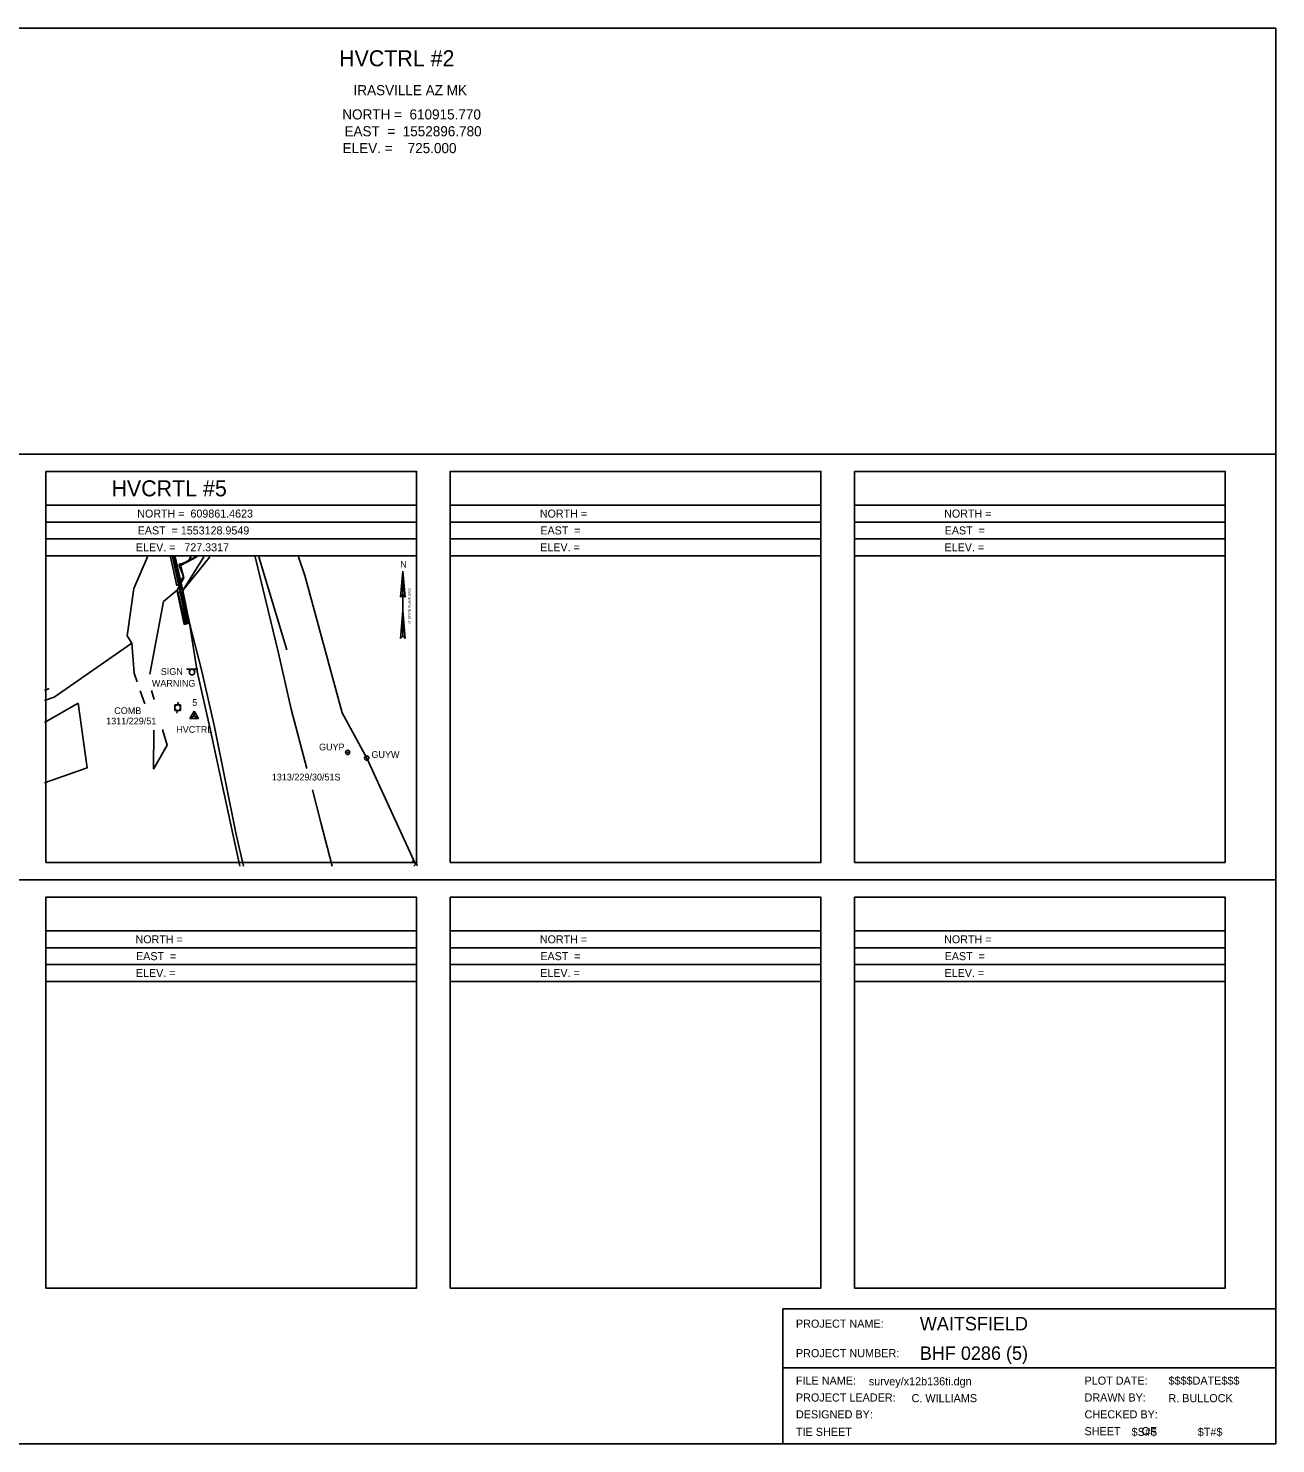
# Model space of a CAD drawing. Extents: x 1553683 to 1554323, y 609712 to 610132.
# Drawn here: x 1553952.8 to 1554323, y 609712.3 to 610132.3 of the extents above; entities that cross this region are included whole.
import ezdxf

# ---------------------------------------------------------------- set-up
doc = ezdxf.new("R2010")
doc.units = 0
for name, color, linetype in [('BDC', 7, 'Continuous'), ('BELB', 7, 'Continuous'), ('BF', 7, 'Continuous'), ('BFT', 7, 'Continuous'), ('BR', 7, 'Continuous'), ('BSE', 7, 'Continuous'), ('BSUBM', 7, 'Continuous'), ('C_A', 7, 'Continuous'), ('C_I', 7, 'Continuous'), ('CPSM', 7, 'Continuous'), ('L_TIC', 7, 'Continuous'), ('LARO', 7, 'Continuous'), ('LAWA', 7, 'Continuous'), ('LAWE', 7, 'Continuous'), ('LELB', 7, 'Continuous'), ('NBL1', 7, 'Continuous'), ('NBL2', 7, 'Continuous'), ('NNA_P', 7, 'Continuous'), ('PET', 7, 'Continuous'), ('RC', 7, 'Continuous'), ('RGR', 7, 'Continuous'), ('S_A', 7, 'Continuous'), ('S_C', 7, 'Continuous'), ('SSGN', 7, 'Continuous'), ('U_A', 7, 'Continuous'), ('U_C', 7, 'Continuous'), ('UP', 7, 'Continuous'), ('UPGW', 7, 'Continuous')]:
    doc.layers.add(name, color=color, linetype=linetype)

msp = doc.modelspace()

# ---------------------------------------------------------------- linework, layer by layer
at = {"layer": 'BDC'}
msp.add_lwpolyline([(1553998.14, 609965.46), (1553995.94, 609975.51)], dxfattribs=at)
at = {"layer": 'BELB'}
for points in [[(1553998.6, 609965.49), (1553996.37, 609975.51)], [(1554004.9, 609975.51), (1553998.6, 609965.49)]]:
    msp.add_lwpolyline(points, dxfattribs=at)
at = {"layer": 'BF'}
msp.add_lwpolyline([(1553994.94, 609975.51), (1553996.84, 609966.88)], dxfattribs=at)
at = {"layer": 'BFT'}
for points in [[(1554000.87, 609975.51), (1554000.67, 609974.99), (1554000.47, 609974.55), (1553998.99, 609973.67), (1553997.4, 609973.19)], [(1554000.36, 609974.24), (1554001.15, 609975.51)]]:
    msp.add_lwpolyline(points, dxfattribs=at)
at = {"layer": 'BR'}
msp.add_lwpolyline([(1553997.86, 609965.15), (1553995.57, 609975.51)], dxfattribs=at)
at = {"layer": 'BSE'}
for points in [[(1554002.85, 609975.51), (1554002.83, 609975.48), (1553997.89, 609972.93)], [(1553998.96, 609969.31), (1553997.89, 609972.93)], [(1553998.96, 609969.31), (1553997.18, 609966.03), (1553997.01, 609965.66)]]:
    msp.add_lwpolyline(points, dxfattribs=at)
at = {"layer": 'BSUBM'}
for points in [[(1554002.37, 609975.51), (1554000.36, 609974.24)], [(1553998.78, 609969.64), (1553997.4, 609973.19)], [(1553997.03, 609966.91), (1553998.78, 609969.64)], [(1553997.01, 609965.66), (1553997.05, 609964.77), (1553999.05, 609955.45), (1554000.57, 609955.79)]]:
    msp.add_lwpolyline(points, dxfattribs=at)
at = {"layer": 'CPSM'}
for p, q in [((1554000.73, 609927.55), (1554001.98, 609929.72)), ((1554000.73, 609927.55), (1554001.98, 609928.27)), ((1554003.23, 609927.55), (1554001.98, 609929.72)), ((1554001.98, 609928.27), (1554001.98, 609929.72)), ((1554001.98, 609928.27), (1554001.98, 609928.27)), ((1554001.98, 609928.27), (1554003.23, 609927.55)), ((1554000.73, 609927.55), (1554003.23, 609927.55))]:
    msp.add_line(p, q, dxfattribs=at)
at = {"layer": 'L_TIC'}
for points in [[(1554068.23, 609883.76), (1554066.72, 609885.27)], [(1554067.14, 609883.68), (1554068.23, 609884.78)], [(1554067.14, 609883.68), (1554068.23, 609884.78)]]:
    msp.add_lwpolyline(points, dxfattribs=at)
at = {"layer": 'LARO'}
for points in [[(1553988.16, 609975.51), (1553984.05, 609966.14), (1553982.1, 609952.03), (1553983.46, 609949.84)], [(1553988.88, 609940.66), (1553992.85, 609962.22), (1553997.01, 609965.66)], [(1553984.19, 609940.93), (1553983.46, 609949.84)], [(1553985.06, 609938.42), (1553984.19, 609940.93)], [(1553987.34, 609931.84), (1553986, 609935.72)], [(1553990.07, 609933.13), (1553989.28, 609935.87)], [(1553989.97, 609912.47), (1553993.96, 609919.56), (1553992.62, 609924.22)], [(1553989.97, 609912.47), (1553990.04, 609924.06)]]:
    msp.add_lwpolyline(points, dxfattribs=at)
at = {"layer": 'LAWA'}
for points in [[(1554032.99, 609975.51), (1554034.79, 609969.93), (1554045.95, 609929.17), (1554053.21, 609915.78), (1554067.72, 609884.27), (1554068.23, 609884.03)], [(1553957.55, 609926.36), (1553967.6, 609932.09)], [(1553957.55, 609908.39), (1553970.2, 609912.87), (1553967.6, 609932.09)]]:
    msp.add_lwpolyline(points, dxfattribs=at)
at = {"layer": 'LAWE'}
msp.add_lwpolyline([(1553983.46, 609949.84), (1553960.43, 609933.88), (1553957.55, 609932.82)], dxfattribs=at)
at = {"layer": 'LELB'}
msp.add_lwpolyline([(1553959, 609936.45), (1553957.55, 609935.87)], dxfattribs=at)
at = {"layer": 'NBL1'}
msp.add_line((1554176.73, 609734.83), (1554322.98, 609734.83), dxfattribs=at)
msp.add_lwpolyline([(1553682.98, 609712.33), (1554322.98, 609712.33), (1554322.98, 610132.33), (1553682.98, 610132.33)], close=True, dxfattribs=at)
msp.add_lwpolyline([(1554322.98, 609752.33), (1554176.73, 609752.33), (1554176.73, 609712.33)], dxfattribs=at)
at = {"layer": 'NBL2'}
for p, q in [((1553682.98, 610005.99), (1554322.98, 610005.99)), ((1554067.98, 609990.83), (1553957.98, 609990.83)), ((1554187.98, 609990.83), (1554077.98, 609990.83)), ((1554307.98, 609990.83), (1554197.98, 609990.83)), ((1554067.98, 609985.83), (1553957.98, 609985.83)), ((1554187.98, 609985.83), (1554077.98, 609985.83)), ((1554307.98, 609985.83), (1554197.98, 609985.83)), ((1554067.98, 609980.83), (1553957.98, 609980.83)), ((1554187.98, 609980.83), (1554077.98, 609980.83)), ((1554307.98, 609980.83), (1554197.98, 609980.83)), ((1554067.98, 609975.83), (1553957.98, 609975.83)), ((1554187.98, 609975.83), (1554077.98, 609975.83)), ((1554307.98, 609975.83), (1554197.98, 609975.83)), ((1553682.98, 609879.66), (1554322.98, 609879.66)), ((1554067.98, 609864.49), (1553957.98, 609864.49)), ((1554187.98, 609864.49), (1554077.98, 609864.49)), ((1554307.98, 609864.49), (1554197.98, 609864.49)), ((1554067.98, 609859.49), (1553957.98, 609859.49)), ((1554187.98, 609859.49), (1554077.98, 609859.49)), ((1554307.98, 609859.49), (1554197.98, 609859.49)), ((1554067.98, 609854.49), (1553957.98, 609854.49)), ((1554187.98, 609854.49), (1554077.98, 609854.49)), ((1554307.98, 609854.49), (1554197.98, 609854.49)), ((1554067.98, 609849.49), (1553957.98, 609849.49)), ((1554187.98, 609849.49), (1554077.98, 609849.49)), ((1554307.98, 609849.49), (1554197.98, 609849.49))]:
    msp.add_line(p, q, dxfattribs=at)
for points in [[(1553957.98, 609884.83), (1554067.98, 609884.83), (1554067.98, 610000.83), (1553957.98, 610000.83)], [(1554077.98, 609884.83), (1554187.98, 609884.83), (1554187.98, 610000.83), (1554077.98, 610000.83)], [(1554197.98, 609884.83), (1554307.98, 609884.83), (1554307.98, 610000.83), (1554197.98, 610000.83)], [(1553957.98, 609758.49), (1554067.98, 609758.49), (1554067.98, 609874.49), (1553957.98, 609874.49)], [(1554077.98, 609758.49), (1554187.98, 609758.49), (1554187.98, 609874.49), (1554077.98, 609874.49)], [(1554197.98, 609758.49), (1554307.98, 609758.49), (1554307.98, 609874.49), (1554197.98, 609874.49)]]:
    msp.add_lwpolyline(points, close=True, dxfattribs=at)
at = {"layer": 'NNA_P'}
for p, q in [((1554063.21, 609963.5), (1554063.91, 609971.29)), ((1554063.91, 609951.92), (1554063.91, 609971.29)), ((1554064.6, 609963.5), (1554063.91, 609971.29)), ((1554063.21, 609963.5), (1554063.91, 609964.27)), ((1554064.6, 609963.5), (1554063.91, 609964.27)), ((1554063.91, 609959.44), (1554063.19, 609951.28)), ((1554063.91, 609959.44), (1554064.63, 609951.28)), ((1554063.91, 609951.92), (1554063.19, 609951.28)), ((1554063.91, 609951.92), (1554064.63, 609951.28))]:
    msp.add_line(p, q, dxfattribs=at)
at = {"layer": 'PET'}
for points in [[(1554016.61, 609883.68), (1554014.46, 609893.13), (1554007.99, 609925.03), (1554004.12, 609941.99), (1554000.57, 609955.79), (1553998.6, 609965.49), (1554006.66, 609975.51)], [(1554035.43, 609912.68), (1554030.82, 609930.31), (1554027.01, 609946.9), (1554020.09, 609975.51)], [(1554042.94, 609883.68), (1554039.62, 609896.63), (1554037.07, 609906.38)]]:
    msp.add_lwpolyline(points, dxfattribs=at)
at = {"layer": 'RC'}
for points in [[(1554000.23, 609955.99), (1553999.75, 609955.86), (1553999.32, 609955.74), (1553997.26, 609964.93), (1553997.86, 609965.15), (1553998.22, 609965.18)], [(1554000.23, 609955.99), (1553998.22, 609965.18)]]:
    msp.add_lwpolyline(points, dxfattribs=at)
at = {"layer": 'RGR'}
for points in [[(1554029.52, 609947.9), (1554021.14, 609975.51)], [(1553999.75, 609955.86), (1553997.86, 609965.15)], [(1554015.59, 609883.68), (1554013.58, 609892.8), (1554006.64, 609924.87), (1554002.84, 609941.47), (1554000.57, 609955.79)]]:
    msp.add_lwpolyline(points, dxfattribs=at)
at = {"layer": 'SSGN'}
for p, q in [((1553999.71, 609942.12), (1554003.04, 609942.12)), ((1554001.35, 609941.29), (1554001.35, 609941.29))]:
    msp.add_line(p, q, dxfattribs=at)
msp.add_circle((1554001.35, 609941.29), 0.833, dxfattribs=at)
at = {"layer": 'UP'}
for p, q in [((1553997.32, 609932.4), (1553997.07, 609931.57)), ((1553996.24, 609929.9), (1553996.24, 609931.57)), ((1553996.24, 609931.57), (1553997.91, 609931.57)), ((1553997.91, 609929.9), (1553996.24, 609929.9)), ((1553996.82, 609929.07), (1553997.07, 609929.9)), ((1553997.07, 609930.74), (1553997.07, 609930.74)), ((1553997.91, 609931.57), (1553997.91, 609929.9))]:
    msp.add_line(p, q, dxfattribs=at)
msp.add_circle((1553997.07, 609930.74), 0.833, dxfattribs=at)
at = {"layer": 'UPGW'}
for centre, radius in [((1554047.55, 609917.45), 0.625), ((1554047.55, 609917.45), 0.0833), ((1554053.21, 609915.78), 0.625), ((1554053.21, 609915.78), 0.0833)]:
    msp.add_circle(centre, radius, dxfattribs=at)

# ---------------------------------------------------------------- texts
at = {"layer": 'C_A'}
msp.add_text('HVCTRL', height=2, dxfattribs=at).set_placement((1553996.67, 609923.27))
at = {"layer": 'C_I'}
msp.add_text('5', height=2, dxfattribs=at).set_placement((1554001.41, 609931.27))
at = {"layer": 'NBL1'}
for s, height, p in [('PROJECT NAME:', 2.4, (1554180.59, 609746.75)), ('WAITSFIELD                ', 4, (1554217.36, 609745.95)), ('PROJECT NUMBER:', 2.4, (1554180.59, 609738)), ('BHF 0286 (5)              ', 4, (1554217.36, 609737.2)), ('FILE NAME:', 2.4, (1554180.59, 609729.84)), ('survey/x12b136ti.dgn      ', 2.4, (1554202.22, 609729.64)), ('PLOT DATE:', 2.4, (1554266.24, 609729.84)), ('$$$$DATE$$$', 2.4, (1554291.17, 609729.84)), ('PROJECT LEADER:', 2.4, (1554180.59, 609724.84)), ('C. WILLIAMS         ', 2.4, (1554214.91, 609724.64)), ('DRAWN BY:', 2.4, (1554266.24, 609724.84)), ('R. BULLOCK   ', 2.4, (1554291.14, 609724.64)), ('DESIGNED BY:', 2.4, (1554180.59, 609719.84)), ('CHECKED BY:', 2.4, (1554266.24, 609719.84)), ('TIE SHEET                         ', 2.4, (1554180.59, 609714.64)), ('SHEET       OF', 2.4, (1554266.24, 609714.84)), ('$S#$ ', 2.4, (1554280.22, 609714.64)), ('$T#$   ', 2.4, (1554299.84, 609714.64))]:
    msp.add_text(s, height=height, dxfattribs=at).set_placement(p)
at = {"layer": 'NBL2'}
for s, height, p in [('     HVCTRL #2     ', 4.75, (1554036.18, 610121.06)), ('   IRASVILLE AZ MK  ', 3, (1554045.95, 610112.48)), ('NORTH =  610915.770 ', 3, (1554045.95, 610105.28)), ('EAST  =  1552896.780', 3, (1554046.6, 610100.28)), ('ELEV. =    725.000  ', 3, (1554046.06, 610095.28)), ('     HVCRTL #5     ', 4.75, (1553968.62, 609993.45)), ('NORTH =  609861.4623', 2.375, (1553985.1, 609987.14)), ('NORTH =             ', 2.375, (1554104.59, 609987.14)), ('NORTH =             ', 2.375, (1554224.59, 609987.14)), ('EAST  = 1553128.9549', 2.375, (1553985.23, 609982.14)), ('EAST  =             ', 2.375, (1554104.74, 609982.14)), ('EAST  =             ', 2.375, (1554224.74, 609982.14)), ('ELEV. =   727.3317  ', 2.375, (1553984.7, 609977.14)), ('ELEV. =             ', 2.375, (1554104.7, 609977.14)), ('ELEV. =             ', 2.375, (1554224.7, 609977.14)), ('NORTH =             ', 2.375, (1553984.59, 609860.81)), ('NORTH =             ', 2.375, (1554104.59, 609860.81)), ('NORTH =             ', 2.375, (1554224.59, 609860.81)), ('EAST  =             ', 2.375, (1553984.74, 609855.81)), ('EAST  =             ', 2.375, (1554104.74, 609855.81)), ('EAST  =             ', 2.375, (1554224.74, 609855.81)), ('ELEV. =             ', 2.375, (1553984.7, 609850.81)), ('ELEV. =             ', 2.375, (1554104.7, 609850.81)), ('ELEV. =             ', 2.375, (1554224.7, 609850.81))]:
    msp.add_text(s, height=height, dxfattribs=at).set_placement(p)
at = {"layer": 'NNA_P'}
msp.add_text('N', height=1.97, dxfattribs=at).set_placement((1554063.15, 609972.3))
msp.add_text('VT STATE PLANE GRID', height=0.7, rotation=90.0204, dxfattribs=at).set_placement((1554066.26, 609955.48))
at = {"layer": 'S_A'}
msp.add_text('SIGN', height=2, dxfattribs=at).set_placement((1553992.09, 609940.46))
at = {"layer": 'S_C'}
msp.add_text('WARNING', height=2, dxfattribs=at).set_placement((1553989.43, 609936.98))
at = {"layer": 'U_A'}
for s, p in [('COMB', (1553978.28, 609928.85)), ('GUYP', (1554039.05, 609918.06)), ('GUYW', (1554054.61, 609915.83))]:
    msp.add_text(s, height=2, dxfattribs=at).set_placement(p)
at = {"layer": 'U_C'}
for s, p in [('1311/229/51', (1553975.88, 609925.78)), ('1313/229/30/51S', (1554025.05, 609909.13))]:
    msp.add_text(s, height=2, dxfattribs=at).set_placement(p)

doc.saveas('drawing.dxf')
